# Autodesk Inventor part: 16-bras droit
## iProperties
Created: 2011-02
Part Number: 16-bras droit
Document SubType Name: Modeling
Designer: eric
Density: 1 g/cm^3
Author: eric
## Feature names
1. Base1
